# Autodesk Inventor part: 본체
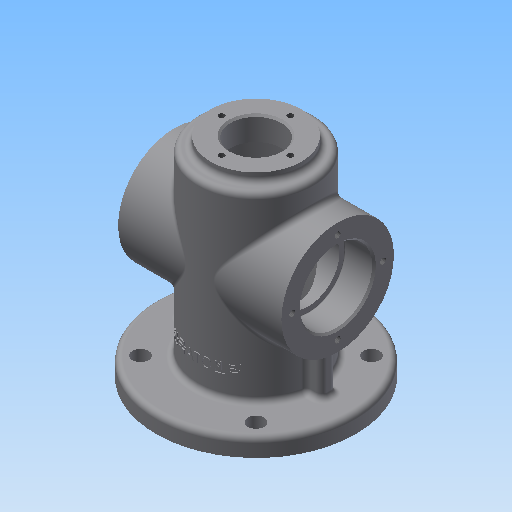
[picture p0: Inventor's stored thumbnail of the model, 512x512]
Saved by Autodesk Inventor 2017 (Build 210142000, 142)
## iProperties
Created: 2020-05
Part Number: 본체
Material: 일반
Document SubType Name: Modeling
Designer: mduedu
Density: 1 g/cm^3
Appearance: 기본값
Mass: 286.81 g
Surface Area: 687.925 cm^2
Volume: 286.81 cm^3
Author: mduedu
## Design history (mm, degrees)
sketch "스케치1"
  geometry: C1 r 32 at (0, 0); 1 further point
  constraints: 1 centre point, 1 coincident
  dimensions: "d0" = 64 diameter of C1
extrude "돌출1" new body sketch "스케치1" distance "d1" = 110; taper "d2" = 0 deg
feature "쉘1" dims "d3" = 8
fillet "모깎기1" dims "d4" = 3
fillet "모깎기2" dims "d5" = 3
sketch "스케치2"
  geometry: C1 r 25 at (0, 0); 1 further point
  constraints: 1 centre point, 1 coincident
  dimensions: "d6" = 50 diameter of C1
extrude "돌출2" join sketch "스케치2" distance "d7" = 5; taper "d8" = 0 deg
sketch "스케치3"
  geometry: C1 r 14 at (0, 0); 1 further point
  constraints: 1 centre point, 1 coincident
  dimensions: "d9" = 28 diameter of C1
extrude "돌출3" cut sketch "스케치3" stored distance "d10" = 5; taper "d11" = 0 deg
fillet "모깎기3" dims "d12" = 3
sketch "스케치4"
  geometry: C1 r 32 at (0, 0) reference; C2 r 55 at (0, 0); 1 further point
  constraints: 1 centre point, 1 coincident
  dimensions: "d13" = 110 diameter of C2
extrude "돌출4" join sketch "스케치4" distance "d14" = 10; taper "d15" = 0 deg
sketch "스케치5"
  geometry: L1 (0, 0)-(-31.82, 31.82); L2 (0, 0)-(-45, 0); A1 r 45 centre (0, 0) between (-31.82, 31.82) and (-45, 0); 1 further point
  constraints: 4 end point, 2 point on circle, 1 centre point, 1 coincident, 1 horizontal
  dimensions: "d16" = 90 diameter of A1; "d71" = 45 deg angle of L1 L2
hole "구멍1" sketch "스케치5" at (-31.82, 31.82) diameter "d17" = 9; stored, may be unused: countersink angle "d21" = 90 deg, drill point angle "d23" = 118 deg; dims "d18" = 6, "d19" = 4, "d20" = 2, "d22" = 8
fillet "모깎기4" dims "d27" = 3
node "작업 평면1"
sketch "스케치6"
  geometry: L1 (0, 55)-(0, -55) reference; C1 r 31 at (-65, 0); 2 further points
  constraints: 1 centre point, 1 horizontal alignment, 1 midpoint
  dimensions: "d31" = 62 diameter of C1; "d32" = 65 distance from line of C1.centre L1
extrude "돌출5" join sketch "스케치6" stored distance "d33" = 10; taper "d34" = 0 deg
fillet "모깎기5" dims "d35" = 3
sketch "스케치7"
  geometry: C1 r 31 at (0, 0) reference; C2 r 20 at (0, 0); 1 further point
  constraints: 1 centre point, 1 coincident
  dimensions: "d36" = 40 diameter of C2
extrude "돌출6" cut sketch "스케치7" distance "d37" = 16; taper "d38" = 0 deg
sketch "스케치8"
  geometry: C1 r 20 at (0, 0) reference; C2 r 17 at (0, 0); 1 further point
  constraints: 1 centre point, 1 coincident
  dimensions: "d39" = 34 diameter of C2
extrude "돌출7" cut sketch "스케치8" stored distance "d40" = 15; taper "d41" = 0 deg
fillet "모깎기6" dims "d42" = 0.3
chamfer "모따기1" distance "d43" = 1; stored, may be unused: second distance "d44" = 2, angle "d45" = 45 deg
chamfer "모따기2" distance "d46" = 1; stored, may be unused: second distance "d47" = 2, angle "d48" = 45 deg
sketch "스케치9" dims "d49" = 50
  geometry: C1 r 31 at (0, 0) reference; 3 further points
  constraints: 2 vertical alignment, 1 coincident, 2 other
hole "구멍2" sketch "스케치9" at (0, 25) diameter "d50" = 3.242; stored, may be unused: countersink angle "d54" = 90 deg, drill point angle "d56" = 118 deg; dims "d51" = 7, "d52" = 4, "d53" = 2, "d55" = 9
sketch "스케치10" dims "d60" = 38
  geometry: 3 further points
  constraints: 2 vertical alignment, 1 coincident, 2 other
hole "구멍3" sketch "스케치10" at (0, 19) diameter "d61" = 3.242; stored, may be unused: countersink angle "d65" = 90 deg, drill point angle "d67" = 118 deg; dims "d62" = 8, "d63" = 4, "d64" = 2, "d66" = 10
sketch "스케치11"
  geometry: L1 (32, 31)-(32, 13) reference; L2 (35, 10)-(52, 10) reference; L3 (55, 7)-(55, 0) reference; L4 (55, 0)-(24, 0) reference; L5 (24, 0)-(24, 48) reference; L6 (24, 48)-(29, 48) reference; L7 (29, 48)-(29, 45.3) reference; L8 (29.3, 45)-(44, 45) reference; L9 (44, 45)-(45, 44) reference; L10 (45, 44)-(45, 41.621) reference; L11 (45, 41.621)-(36, 41.621) reference; L12 (36, 41.621)-(35.026, 40) reference; L13 (35.026, 40)-(36, 38.379) reference; L14 (36, 38.379)-(45, 38.379) reference; L15 (45, 38.379)-(45, 34) reference; L16 (45, 34)-(35, 34) reference; L17 (-32, 13)-(-32, 31) reference; L18 (-35, 34)-(-45, 34) reference; L19 (-45, 34)-(-45, 38.379) reference; L20 (-45, 38.379)-(-36, 38.379) reference; L21 (-36, 38.379)-(-35.026, 40) reference; L22 (-35.026, 40)-(-36, 41.621) reference; L23 (-36, 41.621)-(-45, 41.621) reference; L24 (-45, 41.621)-(-45, 44) reference; L25 (-45, 44)-(-44, 45) reference; L26 (-44, 45)-(-29.3, 45) reference; L27 (-29, 45.3)-(-29, 48) reference; L28 (-29, 48)-(-24, 48) reference; L29 (-24, 48)-(-24, 0) reference; L30 (-24, 0)-(-55, 0) reference; L31 (-55, 0)-(-55, 7) reference; L32 (-52, 10)-(-35, 10) reference; L33 (-25, 113)-(-25, 115) reference; L34 (-25, 115)-(-20.621, 115) reference; L35 (-20.621, 115)-(-20.621, 105) reference; L36 (-20.621, 105)-(-19, 104.026) reference; L37 (-19, 104.026)-(-17.379, 105) reference; L38 (-17.379, 105)-(-17.379, 115) reference; L39 (-17.379, 115)-(-15, 115) reference; L40 (-15, 115)-(-14, 114) reference; L41 (-14, 114)-(-14, 102) reference; L42 (-14, 102)-(-21, 102) reference; L43 (-24, 99)-(-24, 82) reference; L44 (-24, 82)-(-29, 82) reference; L45 (-29, 82)-(-29, 84.7) reference; L46 (-29.3, 85)-(-44, 85) reference; L47 (-44, 85)-(-45, 86) reference; L48 (-45, 86)-(-45, 88.379) reference; L49 (-45, 88.379)-(-36, 88.379) reference; L50 (-36, 88.379)-(-35.026, 90) reference; L51 (-35.026, 90)-(-36, 91.621) reference; L52 (-36, 91.621)-(-45, 91.621) reference; L53 (-45, 91.621)-(-45, 96) reference; L54 (-45, 96)-(-35, 96) reference; L55 (-32, 99)-(-32, 107) reference; L56 (-29, 110)-(-28, 110) reference; L57 (28, 110)-(29, 110) reference; L58 (32, 107)-(32, 99) reference; L59 (35, 96)-(45, 96) reference; L60 (45, 96)-(45, 91.621) reference; L61 (45, 91.621)-(36, 91.621) reference; L62 (36, 91.621)-(35.026, 90) reference; L63 (35.026, 90)-(36, 88.379) reference; L64 (36, 88.379)-(45, 88.379) reference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; A1 r 3 centre (35, 13) between (32, 13) and (35, 10) reference; A2 r 3 centre (52, 7) between (55, 7) and (52, 10) reference; A3 r 0.3 centre (29.3, 45.3) between (29, 45.3) and (29.3, 45) reference; A4 r 0.3 centre (-29.3, 45.3) between (-29.3, 45) and (-29, 45.3) reference; A5 r 3 centre (-52, 7) between (-52, 10) and (-55, 7) reference; A6 r 3 centre (-35, 13) between (-35, 10) and (-32, 13) reference; A7 r 3 centre (-28, 113) between (-28, 110) and (-25, 113) reference; A8 r 3 centre (-21, 99) between (-21, 102) and (-24, 99) reference; A9 r 0.3 centre (-29.3, 84.7) between (-29, 84.7) and (-29.3, 85) reference; A10 r 3 centre (-29, 107) between (-29, 110) and (-32, 107) reference; A11 r 3 centre (28, 113) between (25, 113) and (28, 110) reference; A12 r 3 centre (29, 107) between (32, 107) and (29, 110) reference; A13 r 0.3 centre (29.3, 84.7) between (29.3, 85) and (29, 84.7) reference; A14 r 3 centre (21, 99) between (24, 99) and (21, 102) reference; 1 further point
  constraints: 2 end point, 1 midpoint, 1 perpendicular, 1 point on line, 4 other
  dimensions: "d73" = 5 distance between parallel lines of L81 L19
feature "리브1" sketch "스케치11" dims "d74" = 1, "d75" = 8, "d76" = 0, "d77" = 0, "d78" = 1, "d79" = 1
fillet "모깎기7" dims "d80" = 3
fillet "모깎기8" dims "d81" = 3
node "작업 평면2"
sketch "스케치12"
  geometry: 2 further points
  constraints: 1 vertical alignment, 1 other
  dimensions: "d83" = 25 distance of point (0, 25) point (0, 0)
feature "엠보싱1" sketch "스케치12" dims "d0" = 64, "d84" = 0.5, "d85" = 0
node "솔리드1"
pattern_circular "원형 패턴1" dims angle "d25" = 360 deg
mirror "대칭1"
mirror "대칭2"
pattern_circular "원형 패턴2" dims angle "d58" = 360 deg
mirror "대칭3"
pattern_circular "원형 패턴3" dims angle "d69" = 360 deg
mirror "대칭4"
node "투영된 루프1"
node "투영된 루프2"
node "절단 모서리 투영1"
other parameters: "d30" = -45
